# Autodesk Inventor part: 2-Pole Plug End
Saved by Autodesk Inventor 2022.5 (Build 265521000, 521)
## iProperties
Created: 2024-07
Part Number: 2-Pole Plug End
Material: Generic
Document SubType Name: Modeling
Designer: AdminForWorker
Density: 1 g/cm^3
Appearance: Default
Title: 2-Pole Plug End
Author: AdminForWorker
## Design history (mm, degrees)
feature "2-Pole Plug End"
body "Solid1"
